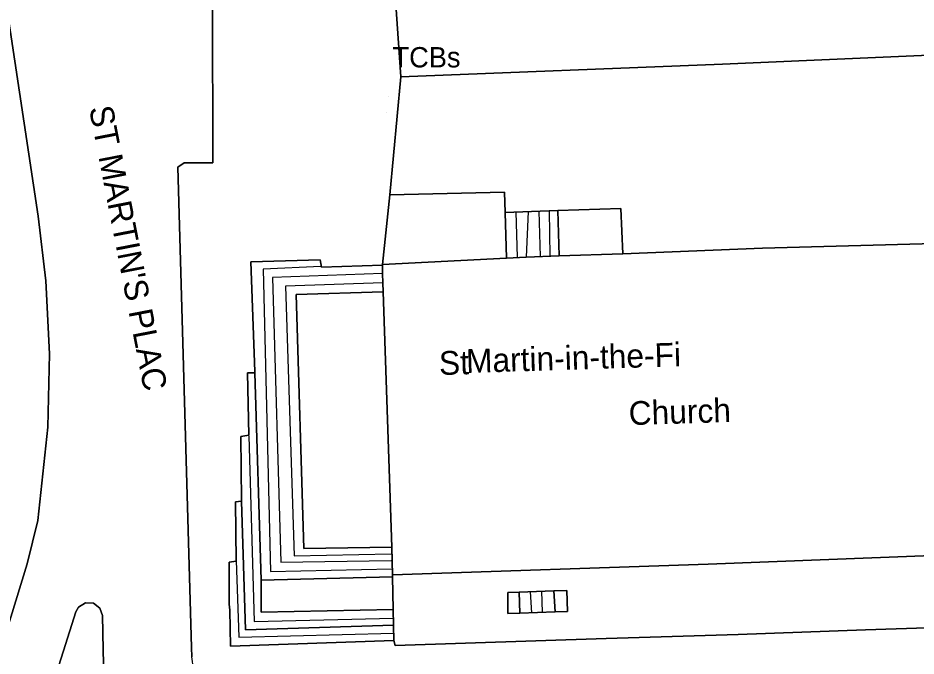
# Model space of a CAD drawing. Extents: x 529240 to 530363, y 179600 to 180767.
# Drawn here: x 530056.2 to 530122.5, y 180522.7 to 180569.8 of the extents above; entities that cross this region are included whole.
import ezdxf

# ---------------------------------------------------------------- set-up
doc = ezdxf.new("R2010")
doc.units = 0
for name, color, linetype in [('Building', 7, 'Continuous'), ('General surface', 7, 'Continuous'), ('Road Or Track', 7, 'Continuous'), ('Roadside', 7, 'Continuous'), ('Structure', 7, 'Continuous'), ('Unclassified', 7, 'Continuous')]:
    doc.layers.add(name, color=color, linetype=linetype)

msp = doc.modelspace()

# ---------------------------------------------------------------- linework, layer by layer
at = {"layer": 'Building'}
for points in [[(530083.13, 180550.2), (530083.15, 180549.55), (530083.8, 180530.7), (530083.85, 180528.65), (530107.15, 180529.45), (530124.3, 180530.1), (530123.85, 180553.1), (530111.15, 180552.75), (530100.85, 180552.35), (530096.15, 180552.19), (530093.7, 180552.1), (530092.25, 180552.02), (530083.1, 180551.55), (530083.1, 180551.5), (530083.12, 180550.9)], [(530083.15, 180549.55), (530076.75, 180549.35), (530077.3, 180530.6), (530083.8, 180530.7)]]:
    msp.add_lwpolyline(points, close=True, dxfattribs=at)
for points in [[(530100.85, 180552.35), (530111.15, 180552.75), (530123.85, 180553.1), (530124.3, 180530.1), (530107.15, 180529.45), (530083.85, 180528.65)], [(530092.25, 180552.02), (530093.7, 180552.1), (530096.15, 180552.19)], [(530096.15, 180552.19), (530100.85, 180552.35)], [(530083.1, 180551.55), (530092.25, 180552.02)], [(530083.1, 180551.5), (530083.1, 180551.55)], [(530083.12, 180550.9), (530083.1, 180551.5)], [(530083.13, 180550.2), (530083.12, 180550.9)], [(530083.15, 180549.55), (530083.13, 180550.2)], [(530083.8, 180530.7), (530077.3, 180530.6), (530076.75, 180549.35), (530083.15, 180549.55)], [(530083.8, 180530.7), (530083.15, 180549.55)], [(530083.85, 180528.65), (530083.8, 180530.7)]]:
    msp.add_lwpolyline(points, dxfattribs=at)
at = {"layer": 'General surface'}
for points in [[(530131.7, 180573.1), (530116.4, 180572.3), (530116.45, 180571.75), (530114.65, 180571.7), (530110.9, 180571.6), (530109.78, 180571.56), (530101.35, 180571.3), (530084.1, 180570.75), (530084.45, 180565.4), (530108.2, 180566.35), (530130.2, 180567.3)], [(530130.2, 180567.3), (530108.2, 180566.35), (530084.45, 180565.4), (530083.65, 180556.7), (530092.1, 180556.9), (530092.15, 180555.4), (530096.05, 180555.54), (530100.7, 180555.7), (530100.85, 180552.35), (530111.15, 180552.75), (530123.85, 180553.1)], [(530095.4, 180555.52), (530095.45, 180552.16)], [(530096.05, 180555.54), (530096.15, 180552.19)], [(530092.15, 180555.4), (530092.25, 180552.02)], [(530092.95, 180555.43), (530093.05, 180552.06)], [(530094.65, 180555.49), (530094.75, 180552.14)], [(530083.1, 180551.5), (530078.6, 180551.35), (530078.5, 180551.9), (530073.4, 180551.75), (530073.7, 180543.65), (530073.7, 180543.55)], [(530078.55, 180551.4), (530074.3, 180551.2), (530074.85, 180528.9), (530083.8, 180529.1)], [(530083.12, 180550.9), (530075, 180550.6), (530075.6, 180529.6), (530083.75, 180529.7)], [(530083.13, 180550.2), (530075.95, 180549.95), (530076.6, 180530.05), (530083.75, 180530.2)], [(530073.7, 180543.55), (530073.15, 180543.55), (530073.25, 180538.95), (530072.65, 180538.85), (530072.7, 180534.15), (530072.7, 180534.1)], [(530073.7, 180543.55), (530074.15, 180528.25)], [(530073.25, 180538.9), (530073.65, 180525.2), (530083.92, 180525.45)], [(530072.7, 180534.1), (530072.25, 180534.05), (530072.3, 180529.65), (530071.8, 180529.6), (530071.8, 180526.49), (530071.85, 180526.05), (530071.9, 180523.4), (530083.95, 180523.8)], [(530072.7, 180534.1), (530073, 180524.6), (530083.93, 180524.95)], [(530072.3, 180529.7), (530072.5, 180524.05), (530083.94, 180524.35)], [(530124.3, 180530.1), (530107.15, 180529.45), (530083.85, 180528.65), (530083.85, 180528.5), (530083.9, 180526.1), (530083.93, 180524.95), (530083.95, 180523.8), (530084.05, 180523.45), (530099.6, 180523.95), (530109.35, 180524.25), (530118.75, 180524.6), (530129.3, 180524.95)], [(530074.15, 180528.25), (530083.85, 180528.5)], [(530074.15, 180528.25), (530074.15, 180525.9), (530083.9, 180526.1)], [(530093.2, 180527.38), (530093.25, 180525.83)], [(530094, 180527.41), (530094.1, 180525.86)], [(530094.85, 180527.44), (530094.9, 180525.89)], [(530095.75, 180527.47), (530095.85, 180525.92)]]:
    msp.add_lwpolyline(points, dxfattribs=at)
for points in [[(530092.15, 180555.4), (530092.1, 180556.9), (530083.65, 180556.7), (530083.1, 180551.55), (530092.25, 180552.02)], [(530092.25, 180552.02), (530093.7, 180552.1), (530096.15, 180552.19), (530096.05, 180555.54), (530092.15, 180555.4)], [(530096.05, 180555.54), (530096.15, 180552.19), (530100.85, 180552.35), (530100.7, 180555.7)], [(530083.12, 180550.9), (530083.1, 180551.5), (530078.6, 180551.35), (530078.5, 180551.9), (530073.4, 180551.75), (530073.7, 180543.65), (530073.7, 180543.55), (530074.15, 180528.25), (530083.85, 180528.5), (530083.85, 180528.65), (530083.8, 180530.7), (530077.3, 180530.6), (530076.75, 180549.35), (530083.15, 180549.55), (530083.13, 180550.2)], [(530083.93, 180524.95), (530083.9, 180526.1), (530074.15, 180525.9), (530074.15, 180528.25), (530073.7, 180543.55), (530073.15, 180543.55), (530073.25, 180538.95), (530072.65, 180538.85), (530072.7, 180534.15), (530072.7, 180534.1), (530073, 180524.6)], [(530072.7, 180534.1), (530072.25, 180534.05), (530072.3, 180529.65), (530071.8, 180529.6), (530071.8, 180526.49), (530071.85, 180526.05), (530071.9, 180523.4), (530083.95, 180523.8), (530083.93, 180524.95), (530073, 180524.6)], [(530083.85, 180528.5), (530074.15, 180528.25), (530074.15, 180525.9), (530083.9, 180526.1)], [(530092.35, 180527.35), (530092.35, 180525.8), (530093.25, 180525.83), (530095.85, 180525.92), (530096.75, 180525.95), (530096.7, 180527.5), (530095.75, 180527.47), (530093.2, 180527.38)], [(530093.2, 180527.38), (530092.35, 180527.35), (530092.35, 180525.8), (530093.25, 180525.83)], [(530093.25, 180525.83), (530095.85, 180525.92), (530095.75, 180527.47), (530093.2, 180527.38)], [(530095.85, 180525.92), (530096.75, 180525.95), (530096.7, 180527.5), (530095.75, 180527.47)]]:
    msp.add_lwpolyline(points, close=True, dxfattribs=at)
at = {"layer": 'Road Or Track'}
for points in [[(530038.318, 180614), (530038.8, 180613.61), (530039.13, 180613.28), (530041.57, 180610.87), (530044.05, 180607.86), (530046.21, 180604.61), (530048.02, 180601.16), (530049.57, 180597.24), (530051.5, 180590.93), (530051.81, 180589.64), (530052.74, 180585.85), (530053.06, 180584.52), (530054.24, 180578.02), (530057.7, 180555.12), (530058.27, 180550.35), (530058.54, 180544.96), (530058.42, 180539.56), (530057.67, 180532.67), (530056.88, 180529.46), (530054.83, 180522.81), (530053.86, 180519.67), (530053.84, 180519.58), (530053.37, 180517.77), (530053.15, 180516.9)], [(530069.03, 180522.59), (530069.01, 180523.29), (530068.01, 180558.74), (530068.48, 180559.06), (530070.58, 180559.07), (530070.57, 180570.77), (530067.21, 180570.76), (530066.84, 180570.93), (530065.39, 180579.19), (530063.66, 180587.1), (530063.26, 180588.57), (530062.26, 180592.29), (530061.55, 180594.92), (530058.96, 180602.86), (530056.95, 180608.24), (530055.43, 180611.51)], [(530069.97, 180519.15), (530069.29, 180520.82), (530069.03, 180522.59), (530069.01, 180523.29), (530068.01, 180558.74), (530068.48, 180559.06), (530070.58, 180559.07), (530070.57, 180570.77), (530067.21, 180570.76), (530066.84, 180570.93), (530065.39, 180579.19), (530063.66, 180587.1), (530063.26, 180588.57), (530062.26, 180592.29), (530061.55, 180594.92), (530058.96, 180602.86)], [(530054.24, 180578.02), (530057.7, 180555.12), (530058.27, 180550.35), (530058.54, 180544.96), (530058.42, 180539.56), (530057.67, 180532.67), (530056.88, 180529.46), (530054.83, 180522.81)], [(530062.67, 180515.77), (530062.62, 180518.01), (530062.5, 180523.11), (530062.44, 180525.64), (530062.25, 180526.2), (530061.78, 180526.56), (530061.19, 180526.59), (530060.69, 180526.27), (530060.49, 180525.92), (530059.57, 180523.04), (530057.93, 180517.89), (530057.32, 180515.98), (530057.48, 180515.43)], [(530057.93, 180517.89), (530059.57, 180523.04), (530060.49, 180525.92), (530060.69, 180526.27), (530061.19, 180526.59), (530061.78, 180526.56), (530062.25, 180526.2), (530062.44, 180525.64), (530062.5, 180523.11), (530062.62, 180518.01)]]:
    msp.add_lwpolyline(points, dxfattribs=at)
at = {"layer": 'Roadside'}
for points in [[(530054.83, 180522.81), (530056.88, 180529.46), (530057.67, 180532.67), (530058.42, 180539.56), (530058.54, 180544.96), (530058.27, 180550.35), (530057.7, 180555.12), (530054.24, 180578.02)], [(530070.57, 180570.77), (530070.58, 180559.07), (530068.48, 180559.06), (530068.01, 180558.74), (530069.01, 180523.29), (530069.03, 180522.59)], [(530129.3, 180524.95), (530118.75, 180524.6), (530109.35, 180524.25), (530099.6, 180523.95), (530084.05, 180523.45), (530083.95, 180523.8), (530071.9, 180523.4), (530071.85, 180526.05), (530071.8, 180526.49), (530071.8, 180529.6), (530072.3, 180529.65), (530072.25, 180534.05), (530072.7, 180534.1), (530072.7, 180534.15), (530072.65, 180538.85), (530073.25, 180538.95), (530073.15, 180543.55), (530073.7, 180543.55), (530073.7, 180543.65), (530073.4, 180551.75), (530078.5, 180551.9), (530078.6, 180551.35), (530083.1, 180551.5), (530083.1, 180551.55), (530083.65, 180556.7), (530084.45, 180565.4), (530084.1, 180570.75)]]:
    msp.add_lwpolyline(points, dxfattribs=at)
msp.add_lwpolyline([(530057.48, 180515.43), (530057.79, 180515.32), (530062.21, 180515.44), (530062.67, 180515.77), (530062.62, 180518.01), (530062.5, 180523.11), (530062.44, 180525.64), (530062.25, 180526.2), (530061.78, 180526.56), (530061.19, 180526.59), (530060.69, 180526.27), (530060.49, 180525.92), (530059.57, 180523.04), (530057.93, 180517.89), (530057.32, 180515.98)], close=True, dxfattribs=at)
at = {"layer": 'Structure'}
for p, q in [((530083.52, 180563.98), (530083.52, 180563.98)), ((530083.41, 180562.78), (530083.41, 180562.78))]:
    msp.add_line(p, q, dxfattribs=at)
at = {"layer": 'Unclassified'}
for points in [[(530084.45, 180565.4), (530084.1, 180570.75)], [(530084.45, 180565.4), (530108.2, 180566.35), (530130.2, 180567.3), (530148, 180568.1), (530148.15, 180564.55)], [(530084.45, 180565.4), (530083.65, 180556.7)], [(530083.65, 180556.7), (530092.1, 180556.9), (530092.15, 180555.4)], [(530083.65, 180556.7), (530083.1, 180551.55)], [(530092.15, 180555.4), (530096.05, 180555.54)], [(530096.05, 180555.54), (530100.7, 180555.7), (530100.85, 180552.35)], [(530093.85, 180555.46), (530093.7, 180552.1)], [(530083.85, 180528.65), (530083.85, 180528.5)], [(530083.85, 180528.5), (530083.9, 180526.1)], [(530093.25, 180525.83), (530092.35, 180525.8), (530092.35, 180527.35), (530093.2, 180527.38)], [(530093.2, 180527.38), (530095.75, 180527.47)], [(530095.75, 180527.47), (530096.7, 180527.5), (530096.75, 180525.95), (530095.85, 180525.92)], [(530083.9, 180526.1), (530083.93, 180524.95)], [(530149.25, 180525.7), (530129.3, 180524.95), (530118.75, 180524.6), (530109.35, 180524.25), (530099.6, 180523.95), (530084.05, 180523.45), (530083.95, 180523.8)], [(530095.85, 180525.92), (530093.25, 180525.83)], [(530083.93, 180524.95), (530083.95, 180523.8)]]:
    msp.add_lwpolyline(points, dxfattribs=at)

# ---------------------------------------------------------------- texts
at = {"layer": 'Road Or Track'}
msp.add_text("ST MARTIN'S PLAC", height=1.75, rotation=281, dxfattribs=at).set_placement((530061.45, 180563.1))
at = {"layer": 'Structure'}
msp.add_text('TCBs', height=1.5, dxfattribs=at).set_placement((530083.85, 180566.1))
at = {"layer": 'Unclassified'}
for s, rotation, p in [('Martin-in-the-Fi', 1.8, (530089.3, 180543.55)), ('St', 1.5, (530087.3, 180543.4)), ('Church', 1.8, (530101.3, 180539.7))]:
    msp.add_text(s, height=1.75, rotation=rotation, dxfattribs=at).set_placement(p)

doc.saveas('drawing.dxf')
